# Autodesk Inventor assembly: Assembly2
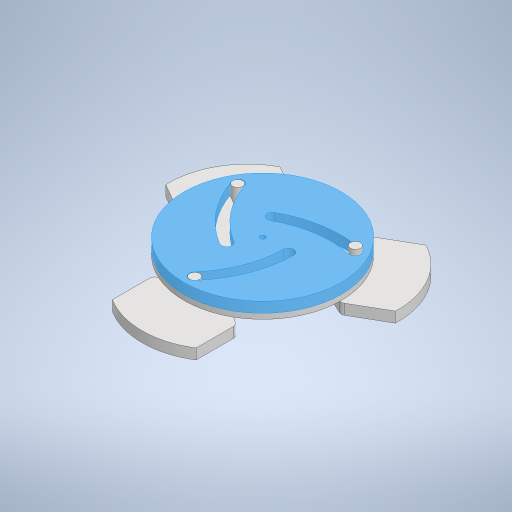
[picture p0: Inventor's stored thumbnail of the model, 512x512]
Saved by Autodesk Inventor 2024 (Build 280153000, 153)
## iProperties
Created: 2024-05
Part Number: Assembly2
Document SubType Name: Assembly
Designer: dylan
Author: dylan
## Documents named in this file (5)
- C:\Users\dylan\OneDrive\Documentos\Universidad\Volta\Airbrakes\Sistema 2\Assembly2.iam
- C:\Users\dylan\OneDrive\Documentos\Universidad\Volta\Airbrakes\Sistema 2\Parte guia_copia.ipt
- C:\Users\dylan\OneDrive\Documentos\Universidad\Volta\Airbrakes\Sistema 2\Giratoria_copia.ipt
- C:\Users\dylan\OneDrive\Documentos\Universidad\Volta\Airbrakes\Sistema 2\Eje transmision_copia.ipt
- C:\Users\dylan\OneDrive\Documentos\Universidad\Volta\Airbrakes\Sistema 2\Part8.ipt
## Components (8 placed, 4 different names)
1. Parte guia_copia:1 — Flush:1, Flush:2, Flush:3, Mate:1, Mate:2, Slider:1, Slider:2, Slider:3
2. Giratoria_copia:1 — Mate:1, Mate:2, Transitional:1, Transitional:2, Transitional:3
3. Eje transmision_copia:1 — Slider:1, Transitional:1, Mate:4, Mate:5, Flush:10
4. Part8:1 — Mate:4, Mate:5, Flush:10
5. Eje transmision_copia:2 — Slider:3, Transitional:3, Mate:6, Flush:12, Flush:13
6. Eje transmision_copia:3 — Slider:2, Transitional:2, Mate:7, Flush:9, Flush:11
7. Part8:2 — Mate:6, Flush:12, Flush:13
8. Part8:3 — Mate:7, Flush:9, Flush:11
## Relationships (20: Flush 8, Mate 6, TranslationJoint 3, Transitional 3)
- Flush:1: Parte guia_copia:1
- Flush:2: Parte guia_copia:1
- Flush:3: Parte guia_copia:1
- Mate:1: Parte guia_copia:1 ↔ Giratoria_copia:1
- Mate:2: Parte guia_copia:1 ↔ Giratoria_copia:1
- Slider:1 [TranslationJoint]: Parte guia_copia:1 ↔ Eje transmision_copia:1
- Transitional:1: Giratoria_copia:1 ↔ Eje transmision_copia:1
- Mate:4: Eje transmision_copia:1 ↔ Part8:1
- Mate:5: Eje transmision_copia:1 ↔ Part8:1
- Slider:2 [TranslationJoint]: Parte guia_copia:1 ↔ Eje transmision_copia:3
- Slider:3 [TranslationJoint]: Parte guia_copia:1 ↔ Eje transmision_copia:2
- Transitional:2: Giratoria_copia:1 ↔ Eje transmision_copia:3
- Transitional:3: Giratoria_copia:1 ↔ Eje transmision_copia:2
- Mate:6: Eje transmision_copia:2 ↔ Part8:2
- Mate:7: Eje transmision_copia:3 ↔ Part8:3
- Flush:9: Eje transmision_copia:3 ↔ Part8:3
- Flush:10: Eje transmision_copia:1 ↔ Part8:1
- Flush:11: Eje transmision_copia:3 ↔ Part8:3
- Flush:12: Eje transmision_copia:2 ↔ Part8:2
- Flush:13: Eje transmision_copia:2 ↔ Part8:2
